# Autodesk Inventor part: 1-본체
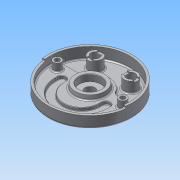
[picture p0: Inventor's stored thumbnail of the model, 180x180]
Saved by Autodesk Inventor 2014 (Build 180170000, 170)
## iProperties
Created: 2015-06
Part Number: 1-본체
Material: 알루미늄 6061
Document SubType Name: Modeling
Designer: Administrator
Density: 2.71 g/cm^3
Appearance: 알루미늄 - 평지
Mass: 1072.06 g
Surface Area: 1037 cm^2
Volume: 395.592 cm^3
Author: Administrator
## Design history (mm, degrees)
sketch "스케치1"
  geometry: C1 r 95 at (0, 0); 1 further point
  constraints: 1 centre point, 1 coincident
  dimensions: "d0" = 190 diameter of C1
extrude "돌출1" new body sketch "스케치1" distance "d1" = 32; taper "d2" = 0 deg
sketch "스케치2"
  geometry: C1 r 95 at (0, 0) reference; C2 r 90 at (0, 0)
  constraints: 1 centre point, 1 coincident
  dimensions: "d3" = 180 diameter of C2
extrude "돌출2" cut sketch "스케치2" distance "d4" = 18; taper "d5" = 0 deg
sketch "스케치3"
  geometry: L1 (-38.833, 16)-(-88.566, 16); L2 (38.833, 16)-(88.566, 16); A1 r 90 centre (0, 0) between (-88.566, 16) and (88.566, 16) reference; A2 r 42 centre (0, 0) between (-38.833, 16) and (38.833, 16)
  constraints: 4 end point, 4 point on circle, 1 centre point, 1 coincident, 1 collinear, 1 horizontal, 1 point on line
  dimensions: "d6" = 84 diameter of A2; "d7" = 16 distance from line of L1 A1.centre
extrude "돌출3" cut sketch "스케치3" distance "d8" = 7; taper "d9" = 0 deg
sketch "스케치4"
  geometry: C1 r 35 at (0, 0); A1 r 42 centre (0, 0) between (38.833, 16) and (-38.833, 16) reference
  constraints: 1 centre point, 1 coincident
  dimensions: "d10" = 70 diameter of C1
extrude "돌출4" join sketch "스케치4" distance "d11" = 10; taper "d12" = -10 deg
sketch "스케치5"
  geometry: L1 (-95, 0)-(95, 0); L2 (0, 0)-(-94.075, -13.221); L3 (0, 0)-(94.075, -13.221); C1 r 90 at (0, 0) reference; A1 r 95 centre (0, 0) between (-95, 0) and (95, 0) reference
  constraints: 6 end point, 4 point on circle, 1 coincident, 1 horizontal, 1 midpoint
  dimensions: "d13" = 8 deg angle of L2 L1; "d14" = 8 deg angle of L3 L1
extrude "돌출5" cut sketch "스케치5" distance "d15" = 5; taper "d16" = 0 deg
sketch "스케치6"
  geometry: L1 (88.566, 16)-(38.833, 16) reference; L2 (-74, 0)-(74, 0); C1 r 35 at (0, 0) reference; C2 r 9 at (-74, 0); C3 r 9 at (74, 0); 1 further point
  constraints: 3 coincident, 2 centre point, 2 end point, 1 midpoint, 1 parallel
  dimensions: "d17" = 148 distance of L2.start L2.end; "d18" = 18 diameter of C2; "d19" = 18 diameter of C3
extrude "돌출6" join sketch "스케치6" stored distance "d20" = 0; taper "d21" = 0 deg
sketch "스케치7"
  geometry: L1 (88.566, 16)-(38.833, 16) reference; L2 (-87.972, -19)-(87.972, -19); L3 (-88.904, -14)-(88.904, -14); L4 (-59, -19)-(-59, -14); L5 (-41, -19)-(-41, -14); L6 (41, -19)-(41, -14); L7 (59, -19)-(59, -14); C1 r 35 at (0, 0) reference; A1 r 90 centre (0, 0) between (-88.566, 16) and (88.566, 16) reference; A2 r 59 centre (0, -19) between (-59, -19) and (59, -19); A3 r 41 centre (0, -19) between (-41, -19) and (41, -19); A4 r 9 centre (-50, -14) between (-41, -14) and (-59, -14); A5 r 9 centre (50, -14) between (59, -14) and (41, -14); 1 further point
  constraints: 12 end point, 11 point on circle, 8 point on line, 8 tangent, 4 centre point, 4 parallel, 2 perpendicular, 1 coincident, 1 midpoint, 1 vertical alignment
  dimensions: "d22" = 118 diameter of A2; "d23" = 19 distance of A2.centre C1.centre; "d24" = 82 diameter of A3; "d25" = 5 distance between parallel lines of L2 L3
extrude "돌출7" cut sketch "스케치7" distance "d26" = 7; taper "d27" = 0 deg
sketch "스케치8"
  geometry: L1 (-38.833, 16)-(-88.566, 16) reference; L2 (-40, 52)-(40, 52); C1 r 15 at (-40, 52); C2 r 15 at (40, 52); A1 r 42 centre (0, 0) between (38.833, 16) and (-38.833, 16) reference; 1 further point
  constraints: 2 centre point, 2 coincident, 2 end point, 1 equal radius, 1 midpoint, 1 parallel, 1 vertical alignment
  dimensions: "d28" = 80 distance of L2.start L2.end; "d29" = 52 distance from line of L2 A1.centre; "d30" = 30 diameter of C1
extrude "돌출8" join sketch "스케치8" stored distance "d31" = 7; taper "d32" = 0 deg
sketch "스케치9"
  geometry: C1 r 95 at (0, 0) reference; C2 r 26 at (0, 0)
  constraints: 1 centre point, 1 coincident
  dimensions: "d33" = 52 diameter of C2
extrude "돌출9" join sketch "스케치9" distance "d34" = 12; taper "d35" = -15 deg
hole "구멍1" diameter "d38" = 23; stored, may be unused: countersink angle "d42" = 90 deg, drill point angle "d44" = 0 deg; dims "d36" = 10, "d37" = 10, "d39" = 6, "d40" = 50, "d41" = 15, "d43" = 8
sketch "스케치10"
  geometry: C1 r 15 at (0, 0) reference; C2 r 15 at (80, 0) reference; 3 further points
  constraints: 2 coincident
hole "구멍2" sketch "스케치10" at (0, 0), (80, 0) diameter "d45" = 20; stored, may be unused: countersink angle "d49" = 90 deg, drill point angle "d51" = 0 deg; dims "d46" = 6, "d47" = 50, "d48" = 15, "d50" = 8
sketch "스케치11"
  geometry: C1 r 9 at (-74, 0) reference; C2 r 9 at (74, 0) reference; 2 further points
  constraints: 2 coincident
hole "구멍3" sketch "스케치11" at (-74, 0), (74, 0) diameter "d52" = 11; stored, may be unused: countersink angle "d56" = 90 deg, drill point angle "d58" = 0 deg; dims "d53" = 6, "d54" = 18, "d55" = 11, "d57" = 8
sketch "스케치12"
  geometry: C1 r 95 at (0, 0) reference; C2 r 68 at (0, 0)
  constraints: 1 centre point, 1 coincident, 1 other
  dimensions: "d59" = 136 diameter of C2
feature "엠보싱1" sketch "스케치12" dims "d1" = 32, "d2" = 0, "d60" = 0.5, "d61" = 0
sketch "스케치13"
  geometry: L1 (-6, 13.748)-(-6, -13.748); L2 (6, 13.748)-(6, -13.748); L3 (66.252, 6)-(93.748, 6); L4 (66.252, -6)-(93.748, -6); C1 r 10 at (80, 0) reference; A1 r 15 centre (0, 0) between (-6, 13.748) and (-6, -13.748) reference; A2 r 15 centre (80, 0) between (66.252, 6) and (93.748, 6) reference; 1 further point
  constraints: 8 end point, 8 point on circle, 4 parallel, 1 perpendicular, 1 vertical
  dimensions: "d62" = 12 distance between parallel lines of L2 L1; "d63" = 12 distance between parallel lines of L4 L3
extrude "돌출10" cut sketch "스케치13" distance "d64" = 3; taper "d65" = 0 deg
chamfer "모따기1" distance "d66" = 1; stored, may be unused: second distance "d67" = 2, angle "d68" = 45 deg
fillet "모깎기1" dims "d69" = 10
fillet "모깎기2" dims "d70" = 10
fillet "모깎기3" dims "d71" = 5, "d72" = 1
fillet "모깎기4" dims "d73" = 0.3
fillet "모깎기5" dims "d74" = 3
fillet "모깎기6" dims "d75" = 3
node "솔리드1"
node "투영된 루프1"
